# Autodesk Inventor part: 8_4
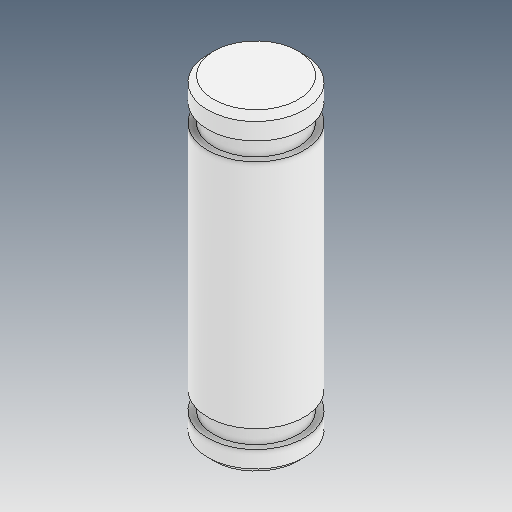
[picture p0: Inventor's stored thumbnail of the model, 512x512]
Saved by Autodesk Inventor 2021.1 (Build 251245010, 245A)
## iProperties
Created: 2021-06
Part Number: 8_4
Material: Ogólny
Document SubType Name: Modeling
Designer: user
Density: 1 g/cm^3
Appearance: Domyślna
Author: user
Revision Number: ÈÎºÎ
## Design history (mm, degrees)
feature "ÊäÈë1"
node "Bryła1"
